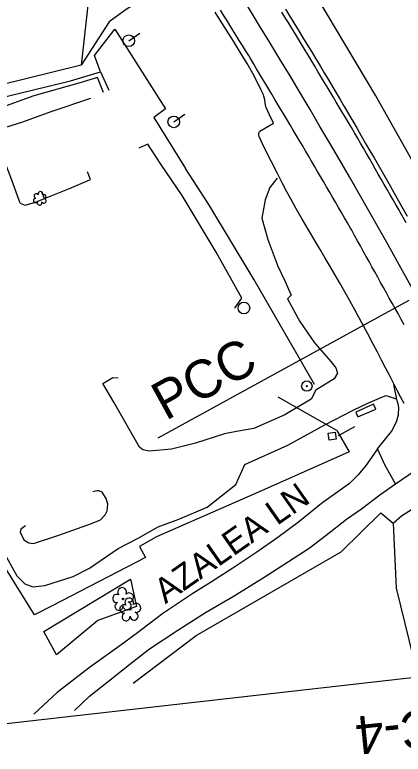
# Model space of a CAD drawing. Extents: x 474972 to 479313, y 498315 to 502691.
# Drawn here: x 477501 to 477663.9, y 499399.9 to 499710.1 of the extents above; entities that cross this region are included whole.
import ezdxf

# ---------------------------------------------------------------- set-up
doc = ezdxf.new("R2010")
doc.units = 0
for name, color, linetype in [('Exist Horizontal Alignment', 7, 'Continuous'), ('Exist Other Culture Area Outline', 7, 'Continuous'), ('Exist Other Culture Fence Line', 7, 'Continuous'), ('Exist Other Culture Gate', 7, 'Continuous'), ('Exist Other Culture Sign', 7, 'Continuous'), ('Exist Roads EOP', 7, 'Continuous'), ('Exist Roads EOP Other', 7, 'Continuous'), ('Exist Roads EOT', 7, 'Continuous'), ('Exist Roads Soil', 7, 'Continuous'), ('Exist Roads Soil Text', 7, 'Continuous'), ('Exist Utilities Other Located Object CELL', 7, 'Continuous'), ('Exist Utilities Other Pole CELL', 7, 'Continuous'), ('Exist Utilities Power Pole CELL', 7, 'Continuous'), ('Exist Vegetation Hedge Row', 7, 'Continuous'), ('Exist Vegetation Shrub CELL', 7, 'Continuous'), ('Exist Vegetation Tree CELL', 7, 'Continuous'), ('Exist Vegetation Woods Line', 7, 'Continuous'), ('Matchline', 7, 'Continuous'), ('Matchline Text', 7, 'Continuous')]:
    doc.layers.add(name, color=color, linetype=linetype)

msp = doc.modelspace()

# ---------------------------------------------------------------- linework, layer by layer
at = {"layer": 'Exist Horizontal Alignment'}
msp.add_line((477666.17, 499590.25), (477560.97, 499532.45), dxfattribs=at)
msp.add_arc((475221.34, 498247), 2793.29, 28.78535, 34.16531, dxfattribs=at)
at = {"layer": 'Exist Other Culture Area Outline'}
msp.add_line((477513.44, 499633.06), (477512.25, 499635.71), dxfattribs=at)
msp.add_lwpolyline([(477513.44, 499633.06), (477523.95, 499637.27), (477532.78, 499640.98), (477531.52, 499644.23)], dxfattribs=at)
for points in [[(477651.45, 499546.76), (477643.98, 499543.46), (477644.89, 499541.42), (477652.35, 499544.71)], [(477632.42, 499534.57), (477635.28, 499535), (477635.71, 499532.15), (477632.85, 499531.72)]]:
    msp.add_lwpolyline(points, close=True, dxfattribs=at)
at = {"layer": 'Exist Other Culture Fence Line'}
msp.add_line((477536.89, 499686.23), (477540.35, 499678.43), dxfattribs=at)
for points in [[(477429.33, 499614.62), (477424.53, 499628.74), (477449.92, 499656.01), (477479.28, 499671.5), (477524.3, 499682.4), (477536.89, 499686.23), (477534.39, 499693.01), (477542.94, 499704), (477564.24, 499670.71), (477559.29, 499667.06), (477572.59, 499645.57)], [(477626.59, 499555.04), (477601.34, 499598.92), (477582.33, 499630.47), (477572.59, 499645.57)], [(477635.96, 499535.67), (477641.13, 499526.75), (477603.17, 499509.91), (477560.47, 499491.13), (477553.33, 499487.13), (477555.79, 499482.43), (477516.59, 499462.19), (477509.3, 499458.35), (477492.2, 499485.62), (477470.2, 499522.98), (477451.45, 499553.86), (477445.3, 499568.14), (477436.76, 499593.23), (477429.33, 499614.62)]]:
    msp.add_lwpolyline(points, dxfattribs=at)
at = {"layer": 'Exist Other Culture Gate'}
msp.add_line((477635.96, 499535.67), (477611.48, 499549.72), dxfattribs=at)
at = {"layer": 'Exist Other Culture Sign'}
msp.add_line((477636.65, 499533.61), (477643.51, 499537.42), dxfattribs=at)
at = {"layer": 'Exist Roads EOP'}
for points in [[(477664.2, 499547.01), (477662.67, 499549.89), (477661.14, 499552.83), (477659.61, 499555.81), (477658.06, 499558.86), (477656.45, 499562.01), (477654.78, 499565.25), (477653.05, 499568.58), (477651.15, 499572.21), (477648.96, 499576.33), (477646.48, 499580.93), (477643.72, 499586.03), (477640.63, 499591.64), (477637.15, 499597.78), (477633.28, 499604.44), (477631.16, 499608.04), (477629.04, 499611.64), (477626.99, 499615.09), (477624.94, 499618.54), (477621.54, 499624.33), (477618.84, 499629.01), (477616.82, 499632.57), (477615.05, 499635.82), (477613.09, 499639.55), (477610.94, 499643.76), (477608.6, 499648.45), (477606.45, 499652.81), (477604.88, 499656.01), (477603.49, 499658.97), (477603.33, 499659.56), (477603.29, 499659.81), (477603.29, 499660.02), (477603.31, 499660.22), (477603.34, 499660.41), (477603.4, 499660.6), (477603.47, 499660.79), (477603.64, 499661.1), (477603.8, 499661.32), (477607.03, 499663.27), (477609.43, 499664.68), (477607.78, 499668.06), (477606.34, 499671.26), (477606.19, 499671.71), (477606.11, 499672.08), (477605.85, 499674.38), (477605.47, 499675.97), (477605.28, 499676.52), (477604.19, 499678.79), (477602.59, 499682.03), (477600.81, 499685.51), (477598.39, 499689.72), (477595.89, 499693.78), (477594.37, 499696.24), (477592.65, 499698.99), (477590.75, 499702.05), (477588.78, 499705.21), (477586.86, 499708.28), (477584.99, 499711.26)], [(477614.46, 499712.45), (477616.18, 499709.63), (477617.95, 499706.74), (477619.78, 499703.78), (477621.63, 499700.77), (477623.48, 499697.75), (477625.33, 499694.71), (477627.18, 499691.66), (477629.01, 499688.64), (477630.77, 499685.7), (477632.47, 499682.86), (477634.11, 499680.11), (477635.74, 499677.35), (477637.41, 499674.5), (477639.13, 499671.56), (477640.9, 499668.52), (477642.69, 499665.44), (477644.49, 499662.35), (477646.29, 499659.25), (477648.11, 499656.14), (477649.9, 499653.07), (477651.64, 499650.05), (477653.34, 499647.09), (477655, 499644.2), (477656.65, 499641.29), (477658.35, 499638.29), (477660.09, 499635.2), (477661.88, 499632.03), (477663.69, 499628.8), (477665.5, 499625.57)]]:
    msp.add_lwpolyline(points, dxfattribs=at)
at = {"layer": 'Exist Roads EOP Other'}
for p, q in [((477661.25, 499548.18), (477659.95, 499555)), ((477660.59, 499513.36), (477674.41, 499522.87))]:
    msp.add_line(p, q, dxfattribs=at)
msp.add_lwpolyline([(477660.59, 499513.36), (477656.3, 499521.06), (477653.1, 499528.09), (477658.99, 499535.35), (477660.99, 499539.3), (477661.81, 499542.32), (477661.99, 499545.35), (477661.68, 499546.94), (477661.25, 499548.18)], dxfattribs=at)
at = {"layer": 'Exist Roads EOT'}
for points in [[(477664.2, 499580.1), (477663, 499582.29), (477661.81, 499584.48), (477661.67, 499584.74), (477660.46, 499586.92), (477659.24, 499589.11), (477658.03, 499591.29), (477656.81, 499593.48), (477655.6, 499595.66), (477654.38, 499597.84), (477653.17, 499600.03), (477651.95, 499602.21), (477650.74, 499604.4), (477649.52, 499606.58), (477648.31, 499608.76), (477647.09, 499610.95), (477645.88, 499613.13), (477644.67, 499615.31), (477643.45, 499617.5), (477642.24, 499619.68), (477641.69, 499620.65), (477640.44, 499622.82), (477639.19, 499624.98), (477637.93, 499627.14), (477636.68, 499629.3), (477635.42, 499631.46), (477634.17, 499633.62), (477632.91, 499635.78), (477631.66, 499637.94), (477630.4, 499640.1), (477629.15, 499642.26), (477627.89, 499644.42), (477626.64, 499646.58), (477625.38, 499648.74), (477624.13, 499650.91), (477622.87, 499653.07), (477621.57, 499655.31), (477620.29, 499657.45), (477619.01, 499659.6), (477617.73, 499661.74), (477616.45, 499663.89), (477615.16, 499666.03), (477613.88, 499668.18), (477612.6, 499670.33), (477611.32, 499672.47), (477610.04, 499674.62), (477608.76, 499676.76), (477607.48, 499678.91), (477606.2, 499681.05), (477604.92, 499683.2), (477603.63, 499685.34), (477602.35, 499687.49), (477601.07, 499689.63), (477599.79, 499691.78), (477599.08, 499692.98), (477597.76, 499695.1), (477596.44, 499697.22), (477595.12, 499699.34), (477593.8, 499701.47), (477592.48, 499703.59), (477591.16, 499705.71), (477589.84, 499707.83), (477588.52, 499709.95), (477587.2, 499712.08)], [(477665.05, 499622.87), (477663.84, 499625.05), (477662.62, 499627.23), (477662.13, 499628.12), (477660.88, 499630.29), (477659.64, 499632.45), (477658.39, 499634.62), (477657.14, 499636.78), (477655.9, 499638.95), (477654.65, 499641.11), (477653.4, 499643.28), (477652.16, 499645.44), (477650.91, 499647.61), (477649.66, 499649.78), (477648.42, 499651.94), (477647.17, 499654.11), (477645.92, 499656.27), (477644.68, 499658.44), (477643.43, 499660.6), (477642.15, 499662.75), (477640.87, 499664.89), (477639.59, 499667.04), (477638.31, 499669.18), (477637.03, 499671.33), (477635.75, 499673.47), (477634.47, 499675.62), (477633.19, 499677.77), (477631.91, 499679.91), (477630.63, 499682.06), (477629.34, 499684.2), (477628.06, 499686.35), (477626.78, 499688.49), (477625.5, 499690.64), (477624.22, 499692.79), (477622.94, 499694.93), (477621.66, 499697.08), (477620.84, 499698.46), (477619.52, 499700.58), (477618.2, 499702.71), (477616.88, 499704.83), (477615.57, 499706.95), (477614.25, 499709.07), (477612.93, 499711.2)]]:
    msp.add_lwpolyline(points, dxfattribs=at)
at = {"layer": 'Exist Roads Soil'}
for points in [[(477538.17, 499677.45), (477535.73, 499683.84), (477527.77, 499681.46), (477508.94, 499676.07), (477492.2, 499670.05), (477483.95, 499666.88), (477476.94, 499664.24), (477471.93, 499662.73), (477458.67, 499657.77), (477448.72, 499651.07), (477436.17, 499638.15), (477435.07, 499628.42), (477436.57, 499618.04)], [(477503.24, 499631.01), (477499.76, 499640.75), (477492.77, 499658.7), (477492.75, 499660.54), (477493.98, 499661.91), (477504.42, 499665.25), (477516.28, 499669.55), (477532.88, 499675.09)], [(477562.26, 499647.37), (477556.79, 499655.83), (477553.55, 499654.44), (477553.03, 499654.18)], [(477593.39, 499586.99), (477593.32, 499587.34), (477596.25, 499591.18), (477585.39, 499610.49), (477571.21, 499634.32), (477562.26, 499647.37)], [(477611.04, 499641.57), (477607.9, 499637.63), (477605.92, 499632.45), (477604.61, 499624.74), (477607.06, 499615.85), (477611.22, 499604.6), (477614.18, 499598.53), (477616.94, 499592.44), (477615.38, 499590.96), (477620.52, 499581.43), (477626.67, 499572.48), (477633.46, 499564.62), (477635.62, 499561.94), (477636.27, 499559.75), (477634.96, 499557.4), (477627.28, 499552.58), (477625.3, 499548.8), (477614.27, 499542.3), (477601.16, 499536.52), (477593.98, 499535.25), (477588.96, 499534.3), (477576.79, 499530.42), (477566.75, 499527.88), (477557.39, 499527.08), (477554.64, 499527.57), (477553.24, 499528.75), (477542.46, 499547.55), (477537.93, 499555.38), (477542.14, 499557.91), (477544.26, 499557.8)], [(477503.24, 499631.01), (477505.39, 499630.24), (477509.68, 499631.56), (477513.44, 499633.06)], [(477496.16, 499485.09), (477501.87, 499474.75), (477505.23, 499471.41), (477508.53, 499470.16), (477513.51, 499470.67), (477525.4, 499474.5), (477532.3, 499478.03), (477544.27, 499486.21), (477552.71, 499490.57), (477561.14, 499495.24), (477569.74, 499498.47), (477581.71, 499503.57), (477593.67, 499513.02), (477597.46, 499521.43), (477615.41, 499529.52), (477630.92, 499538.03), (477642.92, 499544.18), (477648.98, 499547.16), (477654.85, 499549.76), (477656.73, 499550.33), (477660.95, 499549.04)], [(477653.1, 499528.09), (477648.31, 499521.11), (477644.98, 499517.15), (477641.35, 499513.51), (477629.56, 499505.08), (477619.97, 499497.27), (477611.33, 499490.87), (477602.47, 499484.65), (477592.36, 499478), (477583.07, 499471.99), (477575.61, 499467.33), (477563.08, 499458.89), (477551.84, 499450.45), (477545.02, 499445.41), (477532.33, 499436.25), (477518.81, 499425.79), (477508.92, 499416.75)], [(477526.07, 499418.27), (477532.35, 499424.33), (477540.24, 499430.55), (477550.46, 499438.74), (477557.53, 499444.19), (477569.36, 499451.99), (477580.91, 499459.35), (477592.96, 499466.41), (477606.61, 499474.86), (477624.45, 499486.31), (477631.6, 499491.85), (477640.11, 499498.48), (477646.43, 499502.88), (477654.08, 499508.77), (477660.59, 499513.36)], [(477505.45, 499495.68), (477503.52, 499494.28), (477503.2, 499493.05), (477504.82, 499489.92), (477506.87, 499488.6), (477508.88, 499488.36), (477519.5, 499491.8), (477533.2, 499496.68), (477536.89, 499498.23), (477538.81, 499500.31), (477539.72, 499502.08), (477540.05, 499504.82), (477539.32, 499507.26), (477537.6, 499509.92), (477536.41, 499510.45), (477535.33, 499510.48), (477533.76, 499509.98)]]:
    msp.add_lwpolyline(points, dxfattribs=at)
at = {"layer": 'Exist Utilities Other Located Object CELL'}
for radius in [2.18, 0.24]:
    msp.add_circle((477623.43, 499554.34), radius, dxfattribs=at)
at = {"layer": 'Exist Utilities Other Pole CELL'}
msp.add_circle((477597.05, 499587.09), 2.46, dxfattribs=at)
at = {"layer": 'Exist Utilities Power Pole CELL'}
for p, q in [((477548.76, 499699.21), (477553.41, 499702.37)), ((477548.76, 499699.21), (477548.76, 499699.21)), ((477567.65, 499665.18), (477572.29, 499668.35)), ((477567.65, 499665.18), (477567.65, 499665.18))]:
    msp.add_line(p, q, dxfattribs=at)
for centre in [(477548.76, 499699.21), (477567.65, 499665.18)]:
    msp.add_circle(centre, 2.45, dxfattribs=at)
at = {"layer": 'Exist Vegetation Hedge Row'}
for points in [[(477486.39, 499727.41), (477528.65, 499730.51), (477549.21, 499721.35), (477552.29, 499722.77), (477553, 499726.28), (477547.48, 499731.19), (477551.33, 499735.05), (477541.81, 499744.09), (477532.17, 499753.56), (477535.3, 499758.1), (477539.02, 499758.42), (477562.43, 499724.59), (477556.72, 499718.25), (477547.71, 499712.36), (477540.58, 499707.1), (477528.83, 499688.95)], [(477659.61, 499496.91), (477663.15, 499499.97), (477672.75, 499506.09), (477677, 499508.06), (477685.17, 499507.4), (477694.96, 499499.27), (477709.22, 499475.04), (477725.82, 499440.87)]]:
    msp.add_lwpolyline(points, dxfattribs=at)
at = {"layer": 'Exist Vegetation Shrub CELL'}
msp.add_line((477511.53, 499632.91), (477511.53, 499632.91), dxfattribs=at)
for centre, radius, start, end in [((477511.76, 499634.95), 0.99, 334.8391, 200.4717), ((477509.73, 499632.2), 0.955, 95.1099, 327.9534), ((477510.05, 499634.03), 0.968, 35.8908, 245.4216), ((477513.17, 499631.98), 0.937, 204.9913, 73.4601), ((477513.2, 499633.78), 0.929, 284.4567, 126.0861), ((477511.4, 499631.22), 0.984, 151.2797, 21.387)]:
    msp.add_arc(centre, radius, start, end, dxfattribs=at)
at = {"layer": 'Exist Vegetation Tree CELL'}
for p, q in [((477546.38, 499465.08), (477546.38, 499465.08)), ((477549.35, 499460.72), (477549.35, 499460.72))]:
    msp.add_line(p, q, dxfattribs=at)
for centre in [(477546.38, 499465.08), (477549.35, 499460.72)]:
    msp.add_circle(centre, 0.326, dxfattribs=at)
for centre, radius, start, end in [((477545.99, 499467.95), 1.86, 330.1651, 219.7134), ((477543.77, 499465.23), 1.73, 62.6636, 279.3457), ((477548.96, 499463.59), 1.86, 330.1651, 219.7134), ((477548.93, 499465.67), 1.9, 257.1011, 134.1999), ((477544.68, 499461.96), 1.69, 111.5671, 6.231), ((477546.74, 499460.87), 1.73, 62.6636, 279.3457), ((477548.05, 499462.18), 1.7, 181.2822, 74.56), ((477551.9, 499461.31), 1.9, 257.1011, 134.1999), ((477547.64, 499457.6), 1.69, 111.5671, 6.231), ((477551.02, 499457.82), 1.7, 181.2822, 74.56)]:
    msp.add_arc(centre, radius, start, end, dxfattribs=at)
at = {"layer": 'Exist Vegetation Woods Line'}
for points in [[(477652.36, 499676.12), (477598.61, 499766.54)], [(477294.53, 499745.32), (477303.88, 499741.02), (477367.19, 499712.58), (477391.01, 499696.27), (477407.23, 499697.03), (477414.69, 499706.21), (477445.96, 499717.86), (477486.39, 499727.41), (477497.87, 499715.45), (477519.3, 499719.61), (477531.6, 499714.1), (477528.83, 499688.95), (477482.76, 499677.67), (477474.42, 499679.82), (477416.92, 499643.11), (477411.1, 499634.09), (477411.07, 499620.55)], [(477876.38, 499706.59), (477843.58, 499697.18), (477823.77, 499691.04), (477818.96, 499678.19), (477836.09, 499654.48), (477856.54, 499679.3), (477871.93, 499673.78), (477841.32, 499632.8), (477833.17, 499627.98), (477818.22, 499627.52), (477791.9, 499621.51), (477735.64, 499607.74), (477706, 499602.05), (477689.58, 499609.97), (477652.36, 499676.12)], [(477550.66, 499429.73), (477577.08, 499449.67), (477637.89, 499484.83), (477654.45, 499501.19), (477659.61, 499496.91), (477660.87, 499469.61), (477669.88, 499433.14)], [(477513.17, 499451.37), (477549.52, 499473.33), (477552.06, 499461.83), (477535.76, 499455.96), (477518.47, 499441.55), (477513.17, 499451.37)]]:
    msp.add_lwpolyline(points, dxfattribs=at)
at = {"layer": 'Matchline'}
msp.add_line((477986.93, 499468.27), (477490.12, 499411.83), dxfattribs=at)

# ---------------------------------------------------------------- texts
at = {"layer": 'Exist Horizontal Alignment'}
msp.add_text('PCC', height=16, rotation=28.7853, dxfattribs=at).set_placement((477564.27, 499539.65))
at = {"layer": 'Exist Roads Soil Text'}
msp.add_text('AZALEA LN', height=10.4, rotation=35.0405, dxfattribs=at).set_placement((477564.12, 499462.8))
at = {"layer": 'Matchline Text'}
msp.add_text('MATCHLINE SHEET RW02C-4', height=16, rotation=185.8839, dxfattribs=at).set_placement((477942.29, 499446.41))

doc.saveas('drawing.dxf')
